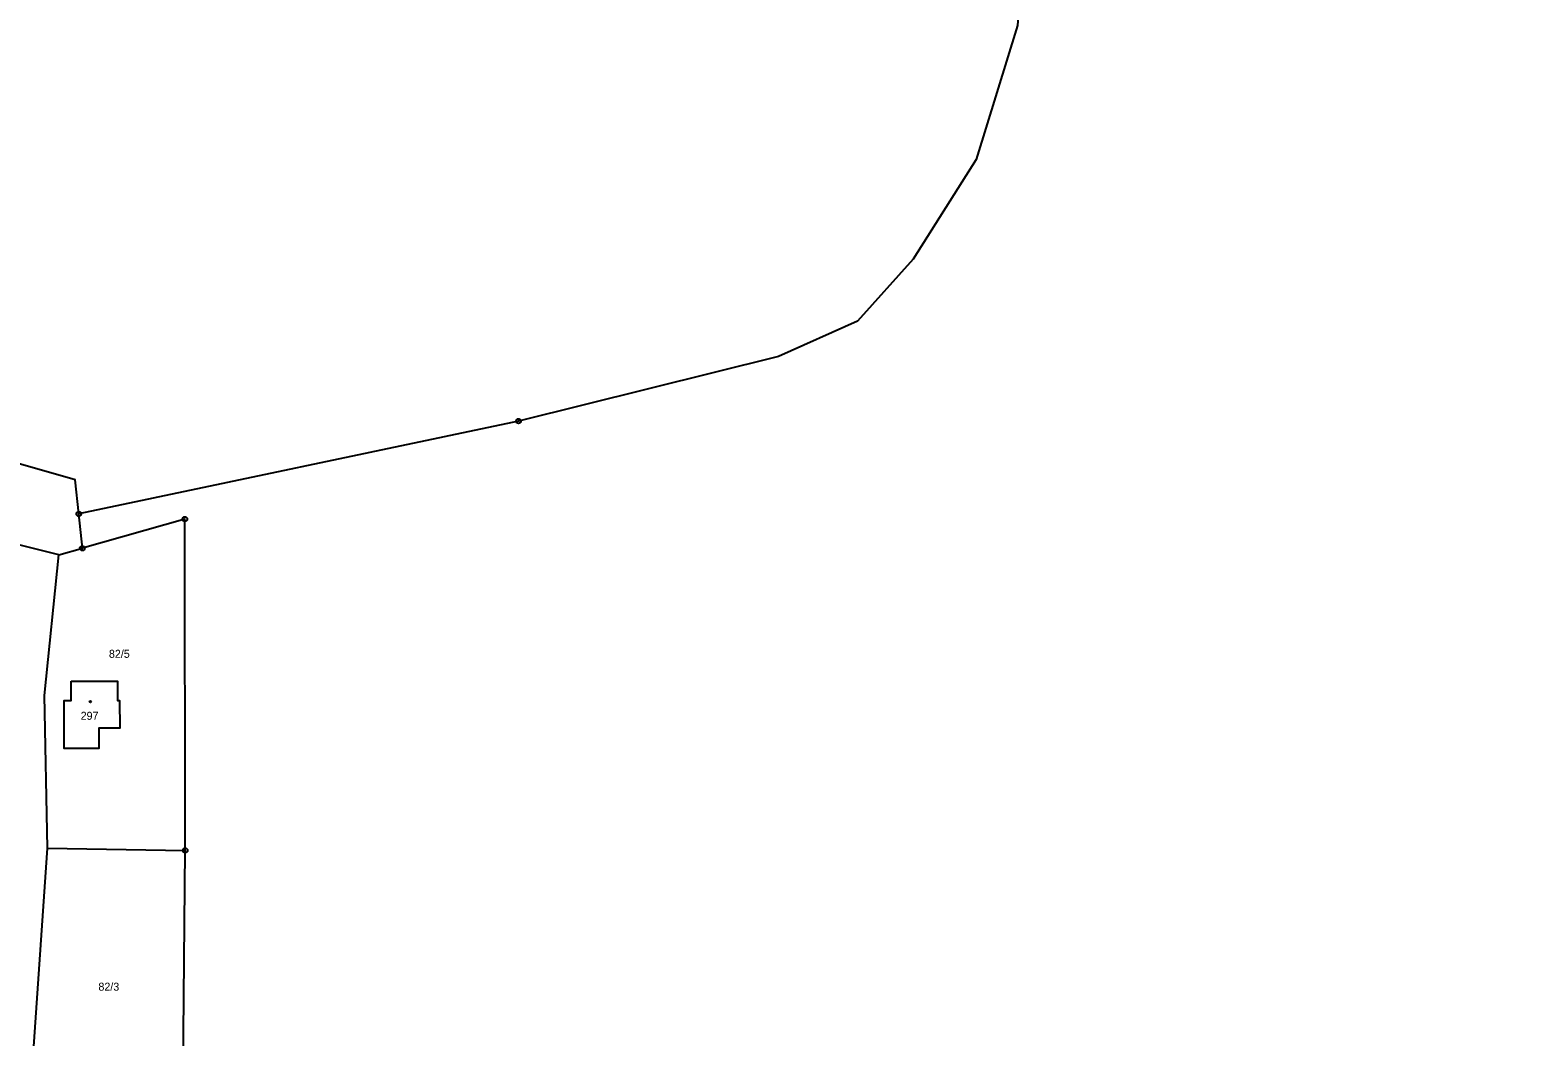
# Model space of a CAD drawing. Extents: x -754445 to -751443, y -1030748 to -1028224.
# Drawn here: x -752358.5 to -752041.3, y -1029103.2 to -1028889.3 of the extents above; entities that cross this region are included whole.
import ezdxf
from ezdxf.enums import TextEntityAlignment as Align

# ---------------------------------------------------------------- set-up
doc = ezdxf.new("R2010")
doc.units = 0
doc.header["$LTSCALE"] = 0.68
for name, color, linetype, lineweight in [('1', 7, 'Continuous', 25), ('5', 7, 'Continuous', 25), ('8', 7, 'Continuous', 25)]:
    doc.layers.add(name, color=color, linetype=linetype, lineweight=lineweight)
doc.layers.add('2', color=7, linetype='Continuous')

msp = doc.modelspace()

# ---------------------------------------------------------------- linework, layer by layer
at = {"layer": '1'}
for p, q in [((-752352.38, -1029000.89), (-752368.47, -1028996.91)), ((-752354.82, -1029063.26), (-752325.54, -1029063.75)), ((-752326.16, -1029133.46), (-752325.54, -1029063.75))]:
    msp.add_line(p, q, dxfattribs=at)
for points in [[(-752003.35, -1028648.05), (-752046.78, -1028655.3), (-752078.41, -1028663.75), (-752092.81, -1028670.68), (-752105.59, -1028687.25), (-752124.43, -1028719.58), (-752129.42, -1028729.32), (-752133.31, -1028748.39), (-752134.61, -1028766.53), (-752138.51, -1028794.36), (-752144.69, -1028823.22), (-752145.93, -1028849.97), (-752148.67, -1028888.34), (-752157.51, -1028916.87), (-752170.84, -1028938.02), (-752182.68, -1028951.22)], [(-752182.68, -1028951.22), (-752199.5, -1028958.7), (-752254.72, -1028972.46), (-752348.16, -1028992.18)], [(-752352.38, -1029000.89), (-752347.4, -1028999.48), (-752348.16, -1028992.18), (-752348.9, -1028984.97), (-752367.07, -1028979.77), (-752369.89, -1028980.83), (-752385.45, -1028986.69)], [(-752325.54, -1029063.75), (-752325.61, -1028993.31), (-752347.4, -1028999.48)], [(-752354.82, -1029063.26), (-752355.47, -1029030.84), (-752352.38, -1029000.89)], [(-752354.25, -1029119.58), (-752357.74, -1029105.45), (-752354.82, -1029063.26)]]:
    msp.add_lwpolyline(points, dxfattribs=at)
msp.add_lwpolyline([(-752349.74, -1029027.74), (-752339.93, -1029027.74), (-752339.94, -1029031.84), (-752339.47, -1029031.84), (-752339.46, -1029037.73), (-752343.87, -1029037.75), (-752343.88, -1029042.09), (-752351.23, -1029042.08), (-752351.25, -1029031.86), (-752349.78, -1029031.86)], close=True, dxfattribs=at)
at = {"layer": '5'}
msp.add_circle((-752345.6868, -1029032.1292), 0.175, dxfattribs=at)
at = {"layer": '8'}
for centre, radius in [((-752254.72, -1028972.4599), 0.5), ((-752254.72, -1028972.4599), 0.0303), ((-752348.16, -1028992.1799), 0.5), ((-752348.16, -1028992.1799), 0.0303), ((-752325.61, -1028993.3099), 0.5), ((-752325.61, -1028993.3099), 0.0303), ((-752347.4, -1028999.4799), 0.5), ((-752347.4, -1028999.4799), 0.0303), ((-752325.54, -1029063.7499), 0.5), ((-752325.54, -1029063.7499), 0.0303)]:
    msp.add_circle(centre, radius, dxfattribs=at)

# ---------------------------------------------------------------- texts
at = {"layer": '2'}
for s, p in [('82/5', (-752339.54, -1029022.79)), ('82/3', (-752341.77, -1029093.57))]:
    msp.add_text(s, height=1.7, dxfattribs=at).set_placement(p, align=Align.CENTER)
msp.add_text('297', height=1.7, dxfattribs=at).set_placement((-752347.76, -1029035.97))

doc.saveas('drawing.dxf')
